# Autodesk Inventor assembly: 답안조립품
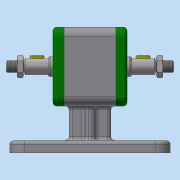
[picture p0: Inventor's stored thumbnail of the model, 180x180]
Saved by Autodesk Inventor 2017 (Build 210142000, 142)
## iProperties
Part Number: 답안조립품
Material: 일반
Document SubType Name: Assembly
Designer: 222
Author: 222
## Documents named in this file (10)
- C:\Users\222\Desktop\701106V1024\답안조립품.iam
- C:\Users\222\Desktop\701106V1024\Ű 5 x 5 x 12.ipt
- C:\Users\222\Desktop\701106V1024\V-벨트풀리.ipt
- C:\Users\222\Desktop\701106V1024\너트 M10x1.ipt
- C:\Users\222\Desktop\701106V1024\베어링 6004.ipt
- C:\Users\222\Desktop\701106V1024\본체.ipt
- C:\Users\222\Desktop\701106V1024\볼트 M4.ipt
- C:\Users\222\Desktop\701106V1024\오일 실 17 30 5.ipt
- C:\Users\222\Desktop\701106V1024\축.ipt
- C:\Users\222\Desktop\701106V1024\커버.ipt
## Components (4 placed, 2 different names)
1. Ű 5 x 5 x 12:2
2. V-벨트풀리:2
3. V-벨트풀리:3
4. Ű 5 x 5 x 12:3
